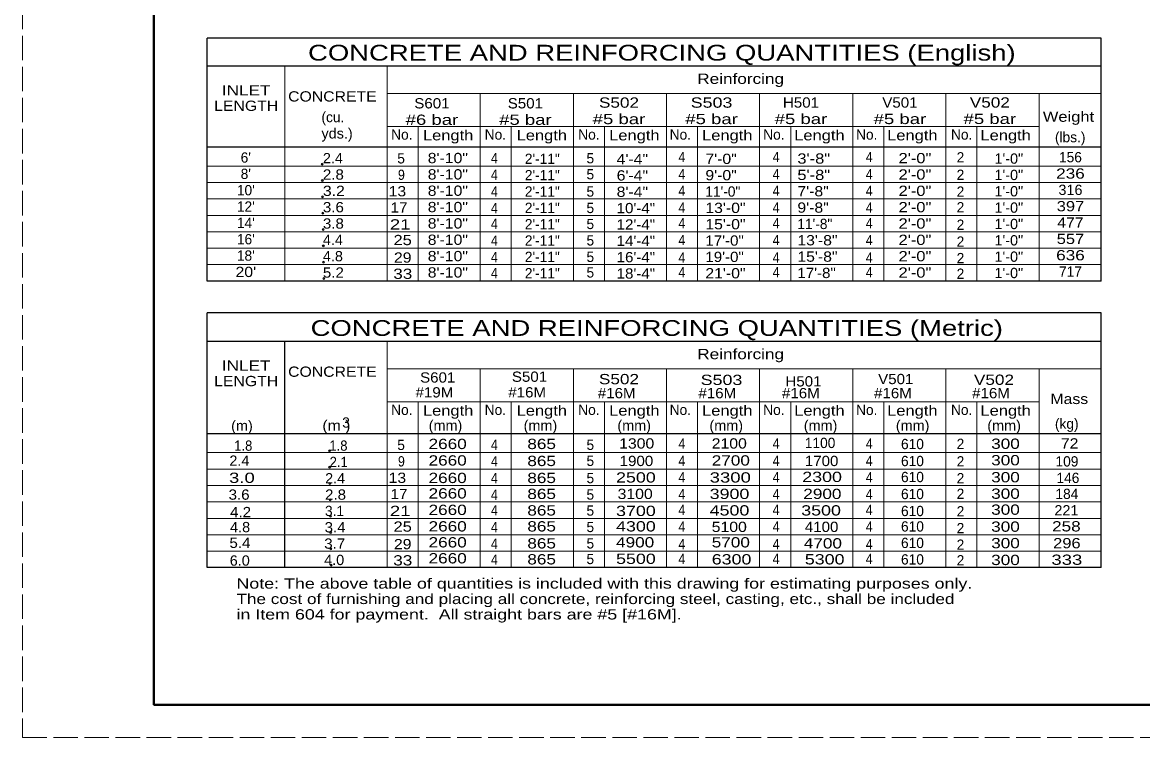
# Model space of a CAD drawing. Extents: x 758.3 to 792.3, y 849.7 to 893.7.
# Drawn here: x 758.32 to 775.35, y 849.69 to 860.56 of the extents above; entities that cross this region are included whole.
import ezdxf
from ezdxf.enums import TextEntityAlignment as Align

# ---------------------------------------------------------------- set-up
doc = ezdxf.new("R2010")
doc.units = 0
doc.header["$LTSCALE"] = 0.062
doc.header["$PDMODE"] = 32
doc.header["$PDSIZE"] = 0.031
doc.linetypes.add('LONG_DASHED', pattern=[7.5, 6, -1.5])
doc.layers.add('1', color=7, linetype='Continuous', lineweight=13)

msp = doc.modelspace()

# ---------------------------------------------------------------- linework, layer by layer
at = {"layer": '1', "lineweight": 25}
for p, q in [((761.12742, 856.62983), (761.12742, 860.32133)), ((774.71917, 860.32133), (761.12742, 860.32133)), ((774.71917, 856.62983), (774.71917, 860.32133)), ((774.71917, 859.89592), (761.12742, 859.89592)), ((774.71917, 858.66542), (761.12742, 858.66542)), ((774.71917, 856.62983), (761.12742, 856.62983)), ((761.12742, 852.2725), (761.12742, 856.14925)), ((774.71917, 856.14925), (761.12742, 856.14925)), ((774.71917, 852.2725), (774.71917, 856.14925)), ((774.71917, 855.71008), (761.12742, 855.71008)), ((762.30742, 852.2725), (762.30742, 855.71008)), ((774.71917, 854.30808), (761.12742, 854.30808)), ((774.71917, 852.2725), (761.12742, 852.2725))]:
    msp.add_line(p, q, dxfattribs=at)
at = {"layer": '1'}
for p, q in [((762.30742, 856.62983), (762.30742, 859.89592)), ((763.86317, 856.62983), (763.86317, 859.89592)), ((774.71917, 859.4795), (763.86317, 859.4795)), ((765.27917, 856.62983), (765.27917, 859.4795)), ((766.69517, 856.62983), (766.69517, 859.4795)), ((768.11117, 856.62983), (768.11117, 859.4795)), ((769.52717, 856.62983), (769.52717, 859.4795)), ((770.94317, 856.62983), (770.94317, 859.4795)), ((772.35917, 856.62983), (772.35917, 859.4795)), ((773.77517, 856.62983), (773.77517, 859.4795)), ((773.77517, 858.97983), (763.86317, 858.97983)), ((764.33517, 856.62983), (764.33517, 858.97983)), ((765.75117, 856.62983), (765.75117, 858.97983)), ((767.16717, 856.62983), (767.16717, 858.97983)), ((768.58317, 856.62983), (768.58317, 858.97983)), ((769.99917, 856.62983), (769.99917, 858.97983)), ((771.41517, 856.62983), (771.41517, 858.97983)), ((772.83117, 856.62983), (772.83117, 858.97983)), ((774.71917, 858.37875), (761.12742, 858.37875)), ((774.71917, 858.12892), (761.12742, 858.12892)), ((774.71917, 857.87908), (761.12742, 857.87908)), ((774.71917, 857.62925), (761.12742, 857.62925)), ((774.71917, 857.37933), (761.12742, 857.37933)), ((774.71917, 857.1295), (761.12742, 857.1295)), ((774.71917, 856.87967), (761.12742, 856.87967)), ((763.86317, 852.2725), (763.86317, 855.71008)), ((774.71917, 855.29367), (763.86317, 855.29367)), ((765.27917, 852.2725), (765.27917, 855.29367)), ((766.69517, 852.2725), (766.69517, 855.29367)), ((768.11117, 852.2725), (768.11117, 855.29367)), ((769.52717, 852.2725), (769.52717, 855.29367)), ((770.94317, 852.2725), (770.94317, 855.29367)), ((772.35917, 852.2725), (772.35917, 855.29367)), ((773.77517, 852.2725), (773.77517, 855.29367)), ((773.77517, 854.794), (763.86317, 854.794)), ((764.33517, 852.2725), (764.33517, 854.794)), ((765.75117, 852.2725), (765.75117, 854.794)), ((767.16717, 852.2725), (767.16717, 854.794)), ((768.58317, 852.2725), (768.58317, 854.794)), ((769.99917, 852.2725), (769.99917, 854.794)), ((771.41517, 852.2725), (771.41517, 854.794)), ((772.83117, 852.2725), (772.83117, 854.794)), ((774.71917, 854.0215), (761.12742, 854.0215)), ((774.71917, 853.77158), (761.12742, 853.77158)), ((774.71917, 853.52175), (761.12742, 853.52175)), ((774.71917, 853.27192), (761.12742, 853.27192)), ((774.71917, 853.02208), (761.12742, 853.02208)), ((774.71917, 852.77217), (761.12742, 852.77217)), ((774.71917, 852.52233), (761.12742, 852.52233))]:
    msp.add_line(p, q, dxfattribs=at)
at = {"layer": '1', "linetype": 'LONG_DASHED'}
msp.add_lwpolyline([(758.3205, 849.68817), (792.3205, 849.68817), (792.3205, 871.68817), (758.3205, 871.68817)], close=True, dxfattribs=at)
at = {"layer": '1', "lineweight": 25}
msp.add_lwpolyline([(791.8205, 850.18817), (760.3205, 850.18817), (760.3205, 871.18817)], dxfattribs=at)
at = {"layer": '1', "lineweight": 40}
msp.add_lwpolyline([(760.3205, 871.18817), (791.8205, 871.18817), (791.8205, 850.18817), (760.3205, 850.18817)], close=True, dxfattribs=at)
at = {"layer": '1'}
for p in [(762.87567, 858.40733), (762.87958, 858.159), (762.88342, 857.91067), (762.88725, 857.66233), (762.89108, 857.41408), (762.89492, 857.16575), (762.89883, 856.91742), (762.90267, 856.66908), (762.98708, 854.05), (762.991, 853.80167), (762.99483, 853.55342), (762.99867, 853.30508), (763.0025, 853.05675), (763.00633, 852.80842), (763.01025, 852.56008), (763.01408, 852.31175)]:
    msp.add_point(p, dxfattribs=at)

# ---------------------------------------------------------------- texts
for s, height, width, p in [('CONCRETE AND REINFORCING QUANTITIES (English)', 0.24, 1.3, (762.66258, 859.98217)), ('yds.)', 0.156, 1.05, (762.8665, 858.79725)), ('Length', 0.156, 1.2, (764.40917, 858.76925)), ('Length', 0.156, 1.2, (765.83325, 858.76925)), ('Length', 0.156, 1.2, (767.23992, 858.76925)), ('Length', 0.156, 1.2, (768.65242, 858.76925)), ('Length', 0.156, 1.2, (770.05325, 858.76925)), ('Length', 0.156, 1.2, (771.46567, 858.76925)), ('Length', 0.156, 1.2, (772.884, 858.76925)), ('2.4', 0.156, 1.05, (762.88808, 858.42108)), ('8\'-10"', 0.156, 1.15, (764.482, 858.42292)), ('4', 0.156, 0.9, (765.44192, 858.41983)), ('4\'-4"', 0.156, 1.15, (767.35367, 858.40708)), ('4', 0.156, 0.9, (768.2925, 858.4385)), ('7\'-0"', 0.156, 1.15, (768.70208, 858.41058)), ('4', 0.156, 0.9, (769.72517, 858.4385)), ('3\'-8"', 0.156, 1.2, (770.10058, 858.41492)), ('4', 0.156, 0.9, (771.14117, 858.4385)), ('2\'-0"', 0.156, 1.2, (771.63842, 858.42142)), ('1\'-0"', 0.156, 1.05, (773.09708, 858.4145)), ('2.8', 0.156, 1.1, (762.88808, 858.17258)), ('9', 0.156, 0.9, (764.02967, 858.16817)), ('8\'-10"', 0.156, 1.15, (764.482, 858.17442)), ('4', 0.156, 0.9, (765.44192, 858.16833)), ('6\'-4"', 0.156, 1.15, (767.35367, 858.15858)), ('4', 0.156, 0.9, (768.2925, 858.17758)), ('9\'-0"', 0.156, 1.15, (768.70208, 858.16208)), ('4', 0.156, 0.9, (769.72517, 858.17758)), ('5\'-8"', 0.156, 1.2, (770.10058, 858.16642)), ('4', 0.156, 0.9, (771.14117, 858.17758)), ('2\'-0"', 0.156, 1.2, (771.63842, 858.17292)), ('1\'-0"', 0.156, 1.05, (773.09708, 858.166)), ('3.2', 0.156, 1.15, (762.88808, 857.92408)), (' 13', 0.156, 1.15, (763.82042, 857.91833)), ('8\'-10"', 0.156, 1.15, (764.482, 857.92592)), ('4', 0.156, 0.9, (765.44192, 857.91208)), ('8\'-4"', 0.156, 1.15, (767.35367, 857.91008)), ('4', 0.156, 0.9, (768.2925, 857.92608)), ('4', 0.156, 0.9, (769.72517, 857.92608)), ('7\'-8"', 0.156, 1.15, (770.10058, 857.91792)), ('4', 0.156, 0.9, (771.14117, 857.92608)), ('2\'-0"', 0.156, 1.2, (771.63842, 857.92442)), ('1\'-0"', 0.156, 1.05, (773.09708, 857.9175)), ('3.6', 0.156, 1.1, (762.88808, 857.67558)), (' 17', 0.156, 1.1, (763.85492, 857.67125)), ('8\'-10"', 0.156, 1.15, (764.482, 857.67742)), ('4', 0.156, 0.9, (765.44192, 857.6605)), ('10\'-4"', 0.156, 1.1, (767.35367, 857.66158)), ('4', 0.156, 0.9, (768.2925, 857.66983)), ('13\'-0"', 0.156, 1.15, (768.70208, 857.66508)), ('4', 0.156, 0.9, (769.72517, 857.66983)), ('9\'-8"', 0.156, 1.15, (770.10058, 857.66942)), ('4', 0.156, 0.9, (771.14117, 857.66983)), ('2\'-0"', 0.156, 1.2, (771.63842, 857.67592)), ('1\'-0"', 0.156, 1.05, (773.09708, 857.669)), ('3.8', 0.156, 1.1, (762.88808, 857.42708)), (' 21 ', 0.156, 1.35, (763.82817, 857.414)), ('8\'-10"', 0.156, 1.15, (764.482, 857.42892)), ('4', 0.156, 0.9, (765.44192, 857.42292)), ('12\'-4"', 0.156, 1.1, (767.35367, 857.41308)), ('4', 0.156, 0.9, (768.2925, 857.43225)), ('15\'-0"', 0.156, 1.15, (768.70208, 857.41658)), ('4', 0.156, 0.9, (769.72517, 857.43225)), ('4', 0.156, 0.9, (771.14117, 857.43225)), ('2\'-0"', 0.156, 1.2, (771.63842, 857.42742)), ('1\'-0"', 0.156, 1.05, (773.09708, 857.4205)), ('4.4', 0.156, 1.05, (762.88808, 857.17858)), ('25', 0.156, 1.2, (763.96192, 857.17625)), ('8\'-10"', 0.156, 1.15, (764.482, 857.18042)), ('4', 0.156, 0.9, (765.44192, 857.16667)), ('14\'-4"', 0.156, 1.1, (767.35367, 857.16458)), ('4', 0.156, 0.9, (768.2925, 857.176)), ('17\'-0"', 0.156, 1.1, (768.70208, 857.16808)), ('4', 0.156, 0.9, (769.72517, 857.176)), ('13\'-8"', 0.156, 1.15, (770.10058, 857.17242)), ('4', 0.156, 0.9, (771.14117, 857.176)), ('2\'-0"', 0.156, 1.2, (771.63842, 857.17892)), ('1\'-0"', 0.156, 1.05, (773.09708, 857.172)), ('4.8', 0.156, 1.05, (762.88808, 856.93008)), ('29', 0.156, 1.15, (763.968, 856.90958)), ('8\'-10"', 0.156, 1.15, (764.482, 856.93192)), ('4', 0.156, 0.9, (765.44192, 856.91517)), ('16\'-4"', 0.156, 1.1, (767.35367, 856.91608)), ('4', 0.156, 0.9, (768.2925, 856.9105)), ('19\'-0"', 0.156, 1.1, (768.70208, 856.91958)), ('4', 0.156, 0.9, (769.72517, 856.9105)), ('15\'-8"', 0.156, 1.15, (770.10058, 856.92392)), ('4', 0.156, 0.9, (771.14117, 856.9105)), ('2\'-0"', 0.156, 1.2, (771.63842, 856.93042)), ('1\'-0"', 0.156, 1.05, (773.09708, 856.9235)), ('5.2', 0.156, 1.1, (762.88808, 856.68158)), ('33', 0.156, 1.25, (763.95733, 856.663)), ('8\'-10"', 0.156, 1.15, (764.482, 856.68342)), ('4', 0.156, 0.9, (765.44192, 856.67292)), ('18\'-4"', 0.156, 1.1, (767.35367, 856.66758)), ('4', 0.156, 0.9, (768.2925, 856.68683)), ('21\'-0"', 0.156, 1.15, (768.70208, 856.67108)), ('4', 0.156, 0.9, (769.72517, 856.68683)), ('17\'-8"', 0.156, 1.1, (770.10058, 856.67542)), ('4', 0.156, 0.9, (771.14117, 856.68683)), ('2\'-0"', 0.156, 1.2, (771.63842, 856.68192)), ('1\'-0"', 0.156, 1.05, (773.09708, 856.675)), ('CONCRETE AND REINFORCING QUANTITIES (Metric)', 0.24, 1.3, (762.70208, 855.79608)), ('#19M', 0.156, 1.1, (764.29658, 854.86042)), ('#16M', 0.156, 1.1, (765.70625, 854.86042)), ('#16M', 0.156, 1.1, (767.06717, 854.84825)), ('#16M', 0.156, 1.1, (768.59658, 854.84825)), ('#16M', 0.156, 1.1, (769.86675, 854.84825)), ('#16M', 0.156, 1.1, (771.26658, 854.84825)), ('#16M', 0.156, 1.1, (772.75708, 854.84825)), ('Length', 0.156, 1.2, (764.40917, 854.58333)), ('Length', 0.156, 1.2, (765.83325, 854.58333)), ('Length', 0.156, 1.2, (767.23992, 854.58333)), ('Length', 0.156, 1.2, (768.65242, 854.58333)), ('Length', 0.156, 1.2, (770.05325, 854.58333)), ('Length', 0.156, 1.2, (771.46567, 854.58333)), ('Length', 0.156, 1.2, (772.884, 854.58333)), ('(m)', 0.156, 1.05, (761.49383, 854.353)), ('(m )', 0.156, 1.15, (762.88033, 854.35733)), ('(mm)', 0.156, 1.05, (764.49683, 854.35733)), ('(mm)', 0.156, 1.05, (765.93942, 854.35733)), ('(mm)', 0.156, 1.05, (767.36467, 854.35733)), ('(mm)', 0.156, 1.05, (768.764, 854.35733)), ('(mm)', 0.156, 1.05, (770.19792, 854.35733)), ('(mm)', 0.156, 1.05, (771.59733, 854.35733)), ('(mm)', 0.156, 1.05, (772.98808, 854.35733)), ('1.8', 0.156, 0.95, (761.54008, 854.05)), ('1.8', 0.156, 0.95, (762.98692, 854.05)), ('2660', 0.156, 1.25, (764.49458, 854.0755)), ('4', 0.156, 0.9, (765.44192, 854.0625)), ('865', 0.156, 1.25, (765.99583, 854.0755)), ('1300', 0.156, 1.15, (767.39142, 854.08333)), ('4', 0.156, 0.9, (768.2925, 854.08117)), ('2100', 0.156, 1.15, (768.79883, 854.08333)), ('4', 0.156, 0.9, (769.72517, 854.08117)), ('4', 0.156, 0.9, (771.14117, 854.08117)), ('300', 0.156, 1.25, (773.04675, 854.07892)), ('2.4', 0.156, 1.05, (761.46658, 853.82158)), ('2.1', 0.156, 0.95, (762.99083, 853.80167)), ('9', 0.156, 0.9, (764.02967, 853.81092)), ('2660', 0.156, 1.25, (764.49458, 853.82492)), ('4', 0.156, 0.9, (765.44192, 853.811)), ('865', 0.156, 1.25, (765.99583, 853.81708)), ('1900', 0.156, 1.1, (767.39925, 853.81708)), ('4', 0.156, 0.9, (768.2925, 853.82033)), ('2700', 0.156, 1.25, (768.79883, 853.82492)), ('4', 0.156, 0.9, (769.72517, 853.82033)), ('1700', 0.156, 1.1, (770.214, 853.81708)), ('4', 0.156, 0.9, (771.14117, 853.82033)), ('300', 0.156, 1.25, (773.04675, 853.82833)), ('3.0 ', 0.156, 1.35, (761.46142, 853.561)), ('2.4', 0.156, 1.05, (762.92217, 853.55342)), (' 13', 0.156, 1.15, (763.82042, 853.561)), ('2660', 0.156, 1.25, (764.49458, 853.55867)), ('4', 0.156, 0.9, (765.44192, 853.55475)), ('865', 0.156, 1.25, (765.99583, 853.55867)), ('2500', 0.156, 1.3, (767.3445, 853.5665)), ('4', 0.156, 0.9, (768.2925, 853.56875)), ('3300', 0.156, 1.35, (768.7675, 853.5665)), ('4', 0.156, 0.9, (769.72517, 853.56875)), ('2300', 0.156, 1.3, (770.17492, 853.57433)), ('4', 0.156, 0.9, (771.14117, 853.56875)), ('300', 0.156, 1.25, (773.04675, 853.56992)), ('3.6', 0.156, 1.1, (761.45483, 853.30508)), ('2.8', 0.156, 1.1, (762.92117, 853.30508)), (' 17', 0.156, 1.1, (763.85492, 853.31392)), ('2660', 0.156, 1.25, (764.49458, 853.32375)), ('4', 0.156, 0.9, (765.44192, 853.30317)), ('865', 0.156, 1.25, (765.99583, 853.31592)), ('3100', 0.156, 1.15, (767.368, 853.31592)), ('4', 0.156, 0.9, (768.2925, 853.3125)), ('3900', 0.156, 1.3, (768.7675, 853.31592)), ('4', 0.156, 0.9, (769.72517, 853.3125)), ('2900', 0.156, 1.25, (770.1905, 853.31592)), ('4', 0.156, 0.9, (771.14117, 853.3125)), ('300', 0.156, 1.25, (773.04675, 853.31933)), ('4.2', 0.156, 1.1, (761.47758, 853.03992)), (' 21 ', 0.156, 1.35, (763.82817, 853.05667)), ('2660', 0.156, 1.25, (764.49458, 853.07317)), ('4', 0.156, 0.9, (765.44192, 853.06558)), ('865', 0.156, 1.25, (765.99583, 853.06533)), ('3700', 0.156, 1.3, (767.3445, 853.0575)), ('4', 0.156, 0.9, (768.2925, 853.07492)), ('4500', 0.156, 1.3, (768.7675, 853.06533)), ('4', 0.156, 0.9, (769.72517, 853.07492)), ('3500', 0.156, 1.3, (770.15925, 853.06533)), ('4', 0.156, 0.9, (771.14117, 853.07492)), ('300', 0.156, 1.25, (773.04675, 853.07658)), ('4.8', 0.156, 1.05, (761.47775, 852.8115)), ('3.4', 0.156, 1.1, (762.91433, 852.80842)), ('25', 0.156, 1.2, (763.96192, 852.81892)), ('2660', 0.156, 1.25, (764.49458, 852.82258)), ('4', 0.156, 0.9, (765.44192, 852.80942)), ('865', 0.156, 1.25, (765.99583, 852.82258)), ('4300', 0.156, 1.3, (767.3445, 852.82258)), ('4', 0.156, 0.9, (768.2925, 852.81867)), ('5100', 0.156, 1.15, (768.79883, 852.81475)), ('4', 0.156, 0.9, (769.72517, 852.81867)), ('4100', 0.156, 1.1, (770.214, 852.81475)), ('4', 0.156, 0.9, (771.14117, 852.81867)), ('300', 0.156, 1.25, (773.04675, 852.81817)), ('5.4', 0.156, 1.1, (761.46783, 852.57233)), ('3.7', 0.156, 1.1, (762.90858, 852.56008)), ('29', 0.156, 1.15, (763.968, 852.55225)), ('2660', 0.156, 1.25, (764.49458, 852.57983)), ('4', 0.156, 0.9, (765.44192, 852.55783)), ('865', 0.156, 1.25, (765.99583, 852.56417)), ('4900', 0.156, 1.25, (767.3445, 852.57983)), ('4', 0.156, 0.9, (768.2925, 852.55317)), ('5700', 0.156, 1.25, (768.79883, 852.57983)), ('4', 0.156, 0.9, (769.72517, 852.55317)), ('4700', 0.156, 1.25, (770.19833, 852.56417)), ('4', 0.156, 0.9, (771.14117, 852.55317)), ('300', 0.156, 1.25, (773.04675, 852.56758)), ('6.0', 0.156, 1.05, (761.47233, 852.30242)), ('4.0', 0.156, 1.05, (762.90758, 852.31175)), ('33', 0.156, 1.25, (763.95733, 852.30567)), ('2660', 0.156, 1.25, (764.49458, 852.33708)), ('4', 0.156, 0.9, (765.44192, 852.31558)), ('865', 0.156, 1.25, (765.99583, 852.32142)), ('5500', 0.156, 1.3, (767.3445, 852.32925)), ('4', 0.156, 0.9, (768.2925, 852.32958)), ('6300', 0.156, 1.3, (768.79883, 852.32142)), ('4', 0.156, 0.9, (769.72517, 852.32958)), ('5300', 0.156, 1.3, (770.214, 852.32142)), ('4', 0.156, 0.9, (771.14117, 852.32958)), ('300', 0.156, 1.25, (773.04675, 852.31175)), ('Note: The above table of quantities is included with this drawing for estimating purposes only.', 0.156, 1.3, (761.57417, 851.95342)), ('The cost of furnishing and placing all concrete, reinforcing steel, casting, etc., shall be included', 0.156, 1.25, (761.57417, 851.71875)), ('in Item 604 for payment.  All straight bars are #5 [#16M].', 0.156, 1.3, (761.57417, 851.48408))]:
    msp.add_text(s, height=height, dxfattribs=dict(at, width=width)).set_placement(p)
for s, width, p in [('Reinforcing', 1.25, (769.23846, 859.62833)), ('INLET', 1.25, (761.72221, 859.45225)), ('CONCRETE', 1.15, (763.03287, 859.36)), ('S601', 1.1, (764.54546, 859.25517)), ('S501', 1.1, (765.96617, 859.25517)), ('S502', 1.25, (767.38904, 859.26583)), ('S503', 1.3, (768.79625, 859.26583)), ('H501', 1.1, (770.15533, 859.267)), ('V501', 1.1, (771.6595, 859.267)), ('V502', 1.25, (773.02629, 859.26808)), ('LENGTH', 1.15, (761.72229, 859.21758)), ('#6 bar', 1.35, (764.54554, 859.00525)), ('#5 bar', 1.35, (765.96621, 859.00533)), ('#5 bar', 1.35, (767.38912, 859.016)), ('#5 bar', 1.35, (768.79637, 859.016)), ('#5 bar', 1.35, (770.15546, 859.01708)), ('#5 bar', 1.35, (771.65954, 859.01708)), ('#5 bar', 1.35, (773.02637, 859.01825)), ('Weight', 1.2, (774.22208, 859.05225)), ('236', 1.25, (774.25192, 858.18767)), ('316', 1.05, (774.25196, 857.93917)), ('397', 1.2, (774.25192, 857.69067)), ('477', 1.15, (774.25187, 857.44217)), ('557', 1.2, (774.25192, 857.19367)), ('636', 1.25, (774.25192, 856.94517)), ("20'", 1.15, (761.71667, 856.69125)), ('Reinforcing', 1.25, (769.23846, 855.44242)), ('INLET', 1.25, (761.72221, 855.26642)), ('CONCRETE', 1.15, (763.03287, 855.17417)), ('LENGTH', 1.15, (761.72229, 855.03175)), ('S601', 1.1, (764.63362, 855.08625)), ('S501', 1.1, (766.02917, 855.098)), ('S502', 1.25, (767.38904, 855.0615)), ('S503', 1.3, (768.9475, 855.04967)), ('H501', 1.1, (770.19317, 855.02708)), ('V501', 1.1, (771.59642, 855.06258)), ('V502', 1.25, (773.08929, 855.05183)), ('Mass', 1.15, (774.23467, 854.76)), ('72', 1.15, (774.23933, 854.08383)), ('221', 1.05, (774.19046, 853.0665)), ('258', 1.25, (774.18988, 852.82308)), ('296', 1.2, (774.19763, 852.56658)), ('333', 1.35, (774.19713, 852.31542))]:
    msp.add_text(s, height=0.156, dxfattribs=dict(at, width=width)).set_placement(p, align=Align.CENTER)
for s, p in [('(cu.', (762.8665, 859.04575)), ('No.', (763.92583, 858.77992)), ('No.', (765.34775, 858.77992)), ('No.', (766.76958, 858.77992)), ('No.', (768.15942, 858.77992)), ('No.', (769.58133, 858.77992)), ('No.', (770.99258, 858.77992)), ('No.', (772.43583, 858.77992)), ('(lbs.)', (774.016, 858.74058)), ('5', (764.019, 858.41808)), ('2\'-11"', (765.958, 858.41108)), ('5', (766.89517, 858.41983)), ('2', (772.52192, 858.43383)), ('2\'-11"', (765.958, 858.16258)), ('5', (766.89517, 858.17633)), ('2', (772.52192, 858.16833)), ('2\'-11"', (765.958, 857.91408)), ('5', (766.89517, 857.91367)), ('11\'-0"', (768.70208, 857.91358)), ('2', (772.52192, 857.91208)), ('2\'-11"', (765.958, 857.66558)), ('5', (766.89517, 857.66375)), ('2', (772.52192, 857.6745)), ('2\'-11"', (765.958, 857.41708)), ('5', (766.89517, 857.42025)), ('11\'-8"', (770.10058, 857.42092)), ('2', (772.52192, 857.40892)), ('2\'-11"', (765.958, 857.16858)), ('5', (766.89517, 857.17033)), ('2', (772.52192, 857.15275)), ('2\'-11"', (765.958, 856.92008)), ('5', (766.89517, 856.92042)), ('2', (772.52192, 856.90117)), ('2\'-11"', (765.958, 856.67158)), ('5', (766.89517, 856.68333)), ('2', (772.52192, 856.66358)), ('No.', (763.92583, 854.59408)), ('No.', (765.34775, 854.59408)), ('No.', (766.76958, 854.59408)), ('No.', (768.15942, 854.59408)), ('No.', (769.58133, 854.59408)), ('No.', (770.99258, 854.59408)), ('No.', (772.43583, 854.59408)), ('3', (763.18217, 854.40158)), ('(kg)', (774.016, 854.38325)), ('5', (764.019, 854.06075)), ('5', (766.89517, 854.0625)), ('1100', (770.214, 854.09117)), ('610', (771.67625, 854.074)), ('2', (772.52192, 854.0765)), ('5', (766.89517, 853.819)), ('610', (771.67625, 853.81558)), ('2', (772.52192, 853.811)), ('5', (766.89517, 853.55633)), ('610', (771.67625, 853.57283)), ('2', (772.52192, 853.55475)), ('5', (766.89517, 853.30642)), ('610', (771.67625, 853.31442)), ('2', (772.52192, 853.31717)), ('3.1', (762.92017, 853.05675)), ('5', (766.89517, 853.06292)), ('610', (771.67625, 853.05608)), ('2', (772.52192, 853.05158)), ('5', (766.89517, 852.813)), ('610', (771.67625, 852.82108)), ('2', (772.52192, 852.79542)), ('5', (766.89517, 852.56308)), ('610', (771.67625, 852.57058)), ('2', (772.52192, 852.54383)), ('5', (766.89517, 852.326)), ('610', (771.67625, 852.32)), ('2', (772.52192, 852.30625))]:
    msp.add_text(s, height=0.156, dxfattribs=at).set_placement(p)
for s, p in [("6'", (761.7165, 858.43075)), ('156', (774.25196, 858.43617)), ("8'", (761.7165, 858.18225)), ("10'", (761.71658, 857.93375)), ("12'", (761.71658, 857.68525)), ("14'", (761.71658, 857.43675)), ("16'", (761.71658, 857.18825)), ("18'", (761.71658, 856.93975)), ('717', (774.25196, 856.69667)), ('109', (774.19842, 853.81042)), ('146', (774.21342, 853.55983)), ('184', (774.19775, 853.31642))]:
    msp.add_text(s, height=0.156, dxfattribs=at).set_placement(p, align=Align.CENTER)

doc.saveas('drawing.dxf')
